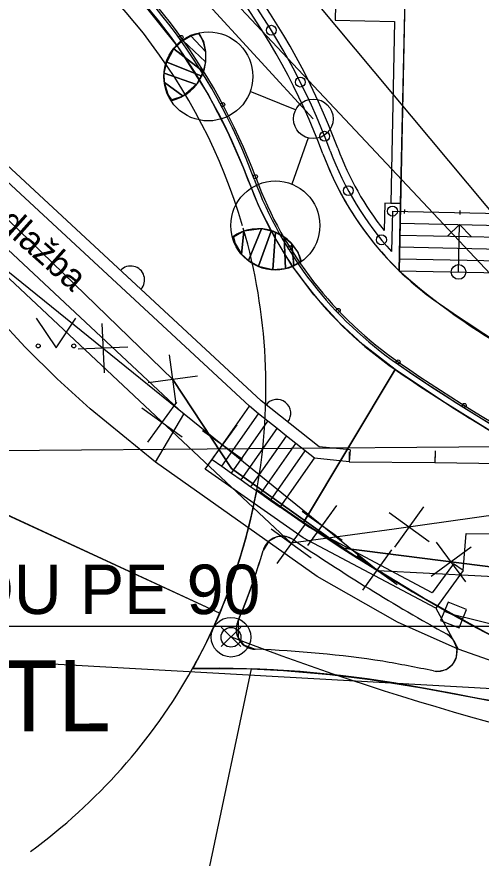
# Model space of a CAD drawing. Extents: x -643342 to -638635, y -1201752 to -1189948.
# Drawn here: x -639484.38 to -639472.65, y -1192725.54 to -1192704.29 of the extents above; entities that cross this region are included whole.
import ezdxf

# ---------------------------------------------------------------- set-up
doc = ezdxf.new("R2010")
doc.units = 0
for name, color, linetype in [('-zbytky_kruháče', 7, 'Continuous'), ('2', 7, 'Continuous'), ('IS_EL_NN_NADZEMNÍ', 7, 'Continuous'), ('IS_PLYN_STL', 7, 'Continuous'), ('IS_TELEF_MISTNI_ZAMERENO', 7, 'Continuous'), ('IS_VODOVOD_VAS', 7, 'Continuous'), ('K-HRANICE_KN', 7, 'Continuous'), ('N-CHODNIK', 7, 'Continuous'), ('N-CHODNIK-PŘÍMĚTICE', 7, 'Continuous'), ('N-HECTOMETRY', 7, 'Continuous'), ('N-KAN_DEST_TRASA-NÁVRH', 7, 'Continuous'), ('N-oploceni', 7, 'Continuous'), ('N-OSA', 7, 'Continuous'), ('N-rusene_vedeni', 7, 'Continuous'), ('N-SILNICE', 7, 'Continuous'), ('N-SRAFY_PLOCHY', 7, 'Continuous'), ('N-vo', 7, 'Continuous'), ('N-ZDI', 7, 'Continuous'), ('N-úprava plochu u obecního úřadu', 7, 'Continuous'), ('tomaštík - Džuganovi - Vrstva 36', 7, 'Continuous'), ('Z-hrany_a_čáry', 7, 'Continuous'), ('Z-popisy', 7, 'Continuous'), ('Z-vchody_vjezdy', 7, 'Continuous'), ('Z-značky', 7, 'Continuous'), ('Z-šachty_poklopy', 7, 'Continuous')]:
    doc.layers.add(name, color=color, linetype=linetype)

# ---------------------------------------------------------------- blocks, each defined once
blk = doc.blocks.new('hecto2')
at = {"layer": 'N-HECTOMETRY'}
blk.add_circle((0, 0), 0.25, dxfattribs=at)
blk = doc.blocks.new('POINT_DISPLAY')
for p, q in [((-0.245, -0.245), (0.245, 0.245)), ((-0.245, 0.245), (0.245, -0.245))]:
    blk.add_line(p, q)
blk = doc.blocks.new('zs')
at = {"layer": 'N-oploceni'}
blk.add_circle((0, 0), 0.05, dxfattribs=at)

msp = doc.modelspace()

# ---------------------------------------------------------------- linework, layer by layer
at = {"layer": '-zbytky_kruháče'}
for centre, radius, start, end in [((-639492.588, -1192713.663), 14.5, 16.3969, 59.8841), ((-639492.588, -1192713.663), 14.5, 349.7654, 16.1456), ((-639492.588, -1192713.663), 14.5, 330.7278, 349.7654), ((-639449.284, -1192676.149), 49.5, 234.0867, 250.3224), ((-639492.588, -1192713.663), 14.5, 306.1426, 330.7278), ((-639479.382, -1192748.546), 27.799, 79.9389, 91.1485), ((-639498.752, -1192857.717), 138.675, 76.30745, 79.93893)]:
    msp.add_arc(centre, radius, start, end, dxfattribs=at)
at = {"layer": '2'}
msp.add_line((-639514.564, -1192719.686), (-639469.586, -1192719.686), dxfattribs=at)
at = {"layer": 'IS_EL_NN_NADZEMNÍ'}
msp.add_line((-639467.47, -1192716.07), (-639488.19, -1192693.98), dxfattribs=at)
msp.add_lwpolyline([(-639485.829, -1192693.153), (-639467.777, -1192714.748)], dxfattribs=at)
at = {"layer": 'IS_PLYN_STL'}
msp.add_lwpolyline([(-639470.24, -1192716.66), (-639471.45, -1192716.75), (-639474.85, -1192717.23), (-639477.45, -1192717.59), (-639486.49, -1192709.11), (-639487.46, -1192707.33), (-639488.82, -1192705.38), (-639489.11, -1192702.85), (-639489.56, -1192702.88), (-639501.83, -1192703.9), (-639502.31, -1192703.92), (-639507.74, -1192703.7), (-639509.62, -1192703.19), (-639512.37, -1192701.73)], dxfattribs=at)
at = {"layer": 'IS_TELEF_MISTNI_ZAMERENO'}
for p, q in [((-639488.01, -1192706.12), (-639480.44, -1192713.45)), ((-639480.44, -1192713.45), (-639478.96, -1192715.7)), ((-639478.96, -1192715.7), (-639480.44, -1192713.45)), ((-639478.96, -1192715.7), (-639476.13, -1192717.71)), ((-639476.13, -1192717.71), (-639478.96, -1192715.7)), ((-639476.13, -1192717.71), (-639470.69, -1192718.41)), ((-639470.69, -1192718.41), (-639476.13, -1192717.71))]:
    msp.add_line(p, q, dxfattribs=at)
at = {"layer": 'IS_VODOVOD_VAS'}
msp.add_lwpolyline([(-639500.03, -1192699), (-639491.62, -1192697.56), (-639487.83, -1192708.11), (-639475.26, -1192718.28), (-639454.38, -1192719.35), (-639371.54, -1192712.72), (-639371.31, -1192712.71), (-639361.553, -1192711.318)], dxfattribs=at)
at = {"layer": 'K-HRANICE_KN'}
msp.add_line((-639430.11, -1192714.81), (-639485.5, -1192715.26), dxfattribs=at)
at = {"layer": 'N-CHODNIK'}
for p, q in [((-639474.553, -1192702.67), (-639474.724, -1192710.703)), ((-639474.84, -1192704.412), (-639474.938, -1192708.998)), ((-639475.088, -1192708.995), (-639475.102, -1192709.69)), ((-639474.938, -1192708.998), (-639474.688, -1192709.004)), ((-639474.698, -1192709.504), (-639471.699, -1192709.568)), ((-639473.199, -1192709.536), (-639473.505, -1192709.829)), ((-639473.224, -1192710.736), (-639473.199, -1192709.536)), ((-639473.199, -1192709.536), (-639472.905, -1192709.842)), ((-639474.705, -1192709.804), (-639471.706, -1192709.868)), ((-639474.711, -1192710.104), (-639471.712, -1192710.168)), ((-639474.717, -1192710.403), (-639471.719, -1192710.468)), ((-639474.724, -1192710.703), (-639471.725, -1192710.768))]:
    msp.add_line(p, q, dxfattribs=at)
msp.add_circle((-639473.224, -1192710.736), 0.185, dxfattribs=at)
at = {"layer": 'N-CHODNIK-PŘÍMĚTICE'}
for centre, radius, start, end in [((-639492.588, -1192713.663), 17, 20.3626, 53.6318), ((-639469.15, -1192704.964), 8, 200.3626, 225.8388)]:
    msp.add_arc(centre, radius, start, end, dxfattribs=at)
at = {"layer": 'N-HECTOMETRY'}
msp.add_circle((-639478.971, -1192719.962), 0.5, dxfattribs=at)
at = {"layer": 'N-KAN_DEST_TRASA-NÁVRH'}
msp.add_lwpolyline([(-639355.755, -1192712.633), (-639405.298, -1192719.503), (-639444.905, -1192722.803), (-639490.998, -1192720.223), (-639511.439, -1192713.331)], dxfattribs=at)
at = {"layer": 'N-oploceni'}
for p, q in [((-639474.591, -1192709.156), (-639474.593, -1192709.256)), ((-639474.892, -1192709.199), (-639474.914, -1192710.22)), ((-639474.892, -1192709.199), (-639471.493, -1192709.272)), ((-639473.191, -1192709.186), (-639473.194, -1192709.286))]:
    msp.add_line(p, q, dxfattribs=at)
for centre in [(-639477.951, -1192704.631), (-639477.22, -1192705.94), (-639476.606, -1192707.308), (-639476.008, -1192708.682), (-639474.892, -1192709.199), (-639475.171, -1192709.924)]:
    msp.add_circle(centre, 0.125, dxfattribs=at)
for centre, radius, start, end in [((-639492.588, -1192713.663), 17.2, 20.3626, 53.6318), ((-639492.588, -1192713.663), 15.2, 20.3626, 54.302), ((-639469.149, -1192704.964), 7.801, 200.3645, 222.363), ((-639469.15, -1192704.964), 9.8, 200.3626, 235.416), ((-639449.284, -1192676.149), 44.8, 235.416, 248.1495)]:
    msp.add_arc(centre, radius, start, end, dxfattribs=at)
at = {"layer": 'N-OSA'}
msp.add_arc((-639452.868, -1192651.78), 73, 249.0487, 271.88891, dxfattribs=at)
at = {"layer": 'N-rusene_vedeni'}
for p, q in [((-639482.23, -1192712.038), (-639482.178, -1192713.286)), ((-639481.579, -1192712.636), (-639482.828, -1192712.688)), ((-639480.356, -1192714.069), (-639480.524, -1192712.831)), ((-639479.821, -1192713.366), (-639481.059, -1192713.534)), ((-639480.346, -1192714.024), (-639481.078, -1192715.037)), ((-639481.219, -1192714.164), (-639480.205, -1192714.896)), ((-639478.822, -1192714.595), (-639479.554, -1192715.609)), ((-639479.695, -1192714.736), (-639478.681, -1192715.468)), ((-639479.52, -1192714.862), (-639478.856, -1192715.342)), ((-639478.948, -1192714.77), (-639479.428, -1192715.434)), ((-639477.176, -1192716.774), (-639476.163, -1192717.506)), ((-639476.304, -1192716.633), (-639477.035, -1192717.646)), ((-639476.43, -1192716.808), (-639476.909, -1192717.472)), ((-639474.98, -1192716.811), (-639473.966, -1192717.543)), ((-639474.107, -1192716.67), (-639474.839, -1192717.683)), ((-639477.001, -1192716.9), (-639476.337, -1192717.379)), ((-639477.957, -1192717.224), (-639476.943, -1192717.956)), ((-639477.084, -1192717.083), (-639477.816, -1192718.097)), ((-639473.038, -1192718.562), (-639473.782, -1192717.558)), ((-639474.916, -1192717.756), (-639475.648, -1192718.769)), ((-639472.908, -1192717.688), (-639473.912, -1192718.432)), ((-639475.788, -1192717.897), (-639474.775, -1192718.628)), ((-639475.614, -1192718.023), (-639474.95, -1192718.502)), ((-639475.042, -1192717.93), (-639475.521, -1192718.594))]:
    msp.add_line(p, q, dxfattribs=at)
at = {"layer": 'N-SILNICE'}
for centre, radius, start, end in [((-639492.588, -1192713.663), 15, 20.3626, 58.4763), ((-639492.588, -1192713.663), 15.15, 20.3626, 54.3132), ((-639469.15, -1192704.964), 10, 200.3626, 235.416), ((-639469.15, -1192704.964), 9.85, 200.3626, 235.416), ((-639449.284, -1192676.149), 45, 235.416, 271.6812), ((-639449.284, -1192676.149), 44.85, 235.416, 262.3092), ((-639449.284, -1192676.149), 44.85, 235.416, 271.2718), ((-639492.588, -1192713.663), 14.5, 330.7278, 349.7654), ((-639449.284, -1192676.149), 49.5, 234.0867, 250.3224), ((-639477.681, -1192717.909), 0.5, 55.7839, 164.1042), ((-639449.284, -1192676.149), 50, 235.7839, 241.0147), ((-639492.588, -1192713.663), 15, 336.8132, 344.1042), ((-639478.34, -1192719.766), 0.5, 156.8132, 267.9262), ((-639473.756, -1192720.324), 0.5, 258.1919, 61.0147), ((-639479.382, -1192748.546), 28.299, 81.3724, 87.9262), ((-639481.925, -1192759.399), 39.42, 78.1919, 80.0854), ((-639479.382, -1192748.546), 27.799, 79.9389, 91.1485), ((-639499.303, -1192860.56), 141.57, 76.54628, 79.92036)]:
    msp.add_arc(centre, radius, start, end, dxfattribs=at)
at = {"layer": 'N-SRAFY_PLOCHY'}
for p, q in [((-639474.552, -1192702.67), (-639474.724, -1192710.703)), ((-639480.316, -1192705.039), (-639481.458, -1192703.607)), ((-639474.688, -1192709.004), (-639474.584, -1192704.167)), ((-639474.84, -1192704.412), (-639474.938, -1192708.998)), ((-639479.56, -1192706.23), (-639480.316, -1192705.039)), ((-639479.049, -1192707.206), (-639479.56, -1192706.23)), ((-639478.655, -1192708.109), (-639479.049, -1192707.206)), ((-639478.268, -1192709.071), (-639478.655, -1192708.109)), ((-639477.884, -1192709.835), (-639478.268, -1192709.071)), ((-639475.088, -1192708.995), (-639475.102, -1192709.69)), ((-639474.688, -1192709.004), (-639475.088, -1192708.995)), ((-639474.938, -1192708.998), (-639474.688, -1192709.004)), ((-639474.724, -1192710.703), (-639474.688, -1192709.004)), ((-639477.432, -1192710.569), (-639477.884, -1192709.835)), ((-639476.875, -1192711.315), (-639477.432, -1192710.569)), ((-639476.226, -1192712.031), (-639476.875, -1192711.315)), ((-639475.645, -1192712.568), (-639476.226, -1192712.031)), ((-639474.827, -1192713.197), (-639475.645, -1192712.568)), ((-639474.826, -1192713.197), (-639477.142, -1192717.065)), ((-639477.142, -1192717.065), (-639474.827, -1192713.197)), ((-639473.628, -1192713.995), (-639474.826, -1192713.197)), ((-639472.421, -1192714.745), (-639473.628, -1192713.995)), ((-639478.45, -1192716.881), (-639478.319, -1192716.239)), ((-639478.319, -1192716.239), (-639477.682, -1192716.693)), ((-639485.157, -1192716.625), (-639479.25, -1192719.35)), ((-639485.157, -1192716.626), (-639479.25, -1192719.352)), ((-639477.682, -1192716.693), (-639477.142, -1192717.065)), ((-639478.641, -1192717.628), (-639478.45, -1192716.881)), ((-639477.142, -1192717.065), (-639475.922, -1192717.87)), ((-639478.941, -1192718.564), (-639478.641, -1192717.628)), ((-639475.922, -1192717.87), (-639474.387, -1192718.811)), ((-639479.25, -1192719.352), (-639478.941, -1192718.564)), ((-639474.387, -1192718.811), (-639473.229, -1192719.472)), ((-639479.25, -1192719.35), (-639479.571, -1192720.051)), ((-639473.229, -1192719.472), (-639471.716, -1192720.274)), ((-639479.571, -1192720.051), (-639479.939, -1192720.752)), ((-639479.939, -1192720.752), (-639479.176, -1192720.75)), ((-639478.462, -1192720.761), (-639479.514, -1192725.747)), ((-639478.463, -1192720.762), (-639479.514, -1192725.747)), ((-639479.176, -1192720.75), (-639478.462, -1192720.761)), ((-639478.065, -1192720.778), (-639478.463, -1192720.762)), ((-639477.222, -1192720.831), (-639478.065, -1192720.778)), ((-639476.475, -1192720.899), (-639477.222, -1192720.831)), ((-639475.757, -1192720.984), (-639476.475, -1192720.899)), ((-639475.155, -1192721.07), (-639475.757, -1192720.984)), ((-639474.526, -1192721.174), (-639475.155, -1192721.07)), ((-639473.783, -1192721.308), (-639474.526, -1192721.174)), ((-639473.038, -1192721.447), (-639473.783, -1192721.308)), ((-639471.837, -1192721.679), (-639473.038, -1192721.447))]:
    msp.add_line(p, q, dxfattribs=at)
for points in [[(-639476.204, -1192698.396), (-639476.343, -1192704.379), (-639474.84, -1192704.412)], [(-639472.367, -1192719.938), (-639474.117, -1192718.966), (-639475.491, -1192718.134), (-639476.532, -1192717.468), (-639477.142, -1192717.065), (-639477.682, -1192716.693), (-639478.319, -1192716.239), (-639478.545, -1192717.254), (-639478.791, -1192718.096), (-639479.096, -1192718.958), (-639479.411, -1192719.702), (-639479.649, -1192720.208), (-639479.94, -1192720.753), (-639479.177, -1192720.751), (-639478.463, -1192720.762), (-639477.644, -1192720.805), (-639476.475, -1192720.9), (-639475.456, -1192721.028), (-639474.155, -1192721.242), (-639472.841, -1192721.484), (-639471.453, -1192721.756)], [(-639477.4, -1192717.495), (-639477.58, -1192717.419), (-639477.812, -1192717.426), (-639478.014, -1192717.536), (-639478.162, -1192717.772)], [(-639478.793, -1192719.554), (-639478.793, -1192719.978), (-639478.658, -1192720.152), (-639478.358, -1192720.266)], [(-639473.858, -1192720.813), (-639473.729, -1192720.823), (-639473.54, -1192720.775), (-639473.372, -1192720.644), (-639473.273, -1192720.456), (-639473.261, -1192720.25), (-639473.361, -1192720.016), (-639473.513, -1192719.886)]]:
    msp.add_lwpolyline(points, dxfattribs=at)
for centre, radius, start, end in [((-639492.588, -1192713.663), 17.4, 20.3626, 53.6318), ((-639492.588, -1192713.663), 17, 20.3626, 53.6318), ((-639492.588, -1192713.663), 17, 20.3626, 53.6318), ((-639492.588, -1192713.663), 15, 20.3626, 54.3482), ((-639469.15, -1192704.964), 7.6, 200.3626, 218.4504), ((-639469.15, -1192704.964), 8, 200.3626, 235.416), ((-639469.15, -1192704.964), 8, 200.3626, 225.8388), ((-639469.15, -1192704.964), 10, 200.3626, 235.416), ((-639463.769, -1192698.406), 16.47, 228.3034, 240.9372), ((-639449.284, -1192676.149), 43, 235.416, 246.7221), ((-639449.284, -1192676.149), 45, 235.416, 245.5943), ((-639477.681, -1192717.909), 0.5, 55.7839, 164.1042), ((-639449.283, -1192676.148), 50.001, 235.784, 241.0146), ((-639449.284, -1192676.149), 50, 235.7839, 241.0147), ((-639492.588, -1192713.663), 15, 336.8132, 344.1042), ((-639492.588, -1192713.663), 15, 336.8787, 344.1042), ((-639478.34, -1192719.766), 0.5, 156.8132, 267.9243), ((-639473.756, -1192720.324), 0.5, 258.1522, 61.0147), ((-639479.382, -1192748.546), 28.299, 81.3724, 87.9262), ((-639478.34, -1192719.766), 0.5, 267.9245, 267.9263), ((-639479.382, -1192748.546), 28.299, 87.92619045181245, 87.92619290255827), ((-639478.34, -1192719.766), 0.5, 267.9243, 267.9245), ((-639479.382, -1192748.546), 28.299, 87.92616076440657, 87.92619045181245), ((-639478.34, -1192719.766), 0.5, 267.9245, 267.9262), ((-639479.382, -1192748.546), 28.299, 81.3724, 87.9262), ((-639481.77, -1192758.593), 38.599, 78.1722, 80.1055), ((-639481.925, -1192759.399), 39.42, 78.1919, 80.0854)]:
    msp.add_arc(centre, radius, start, end, dxfattribs=at)
at = {"layer": 'N-vo'}
for p, q in [((-639484.101, -1192699.004), (-639476.892, -1192706.867)), ((-639477.338, -1192706.64), (-639478.488, -1192706.18)), ((-639477.018, -1192707.35), (-639477.438, -1192708.516))]:
    msp.add_line(p, q, dxfattribs=at)
for points in [[(-639480.188, -1192704.885), (-639479.613, -1192705.43), (-639479.673, -1192705.674), (-639480.418, -1192705.103)], [(-639479.988, -1192704.771), (-639479.619, -1192705.168), (-639479.613, -1192705.43), (-639480.188, -1192704.885)], [(-639479.789, -1192704.713), (-639479.662, -1192704.916), (-639479.619, -1192705.168), (-639479.988, -1192704.771)], [(-639480.418, -1192705.103), (-639479.673, -1192705.674), (-639479.724, -1192705.78), (-639480.593, -1192705.435)], [(-639480.593, -1192705.435), (-639479.724, -1192705.78), (-639479.841, -1192706.001), (-639480.656, -1192705.714)], [(-639480.656, -1192705.714), (-639479.841, -1192706.001), (-639480.182, -1192706.294), (-639480.652, -1192705.954)], [(-639480.652, -1192705.954), (-639480.182, -1192706.294), (-639480.469, -1192706.391), (-639480.558, -1192706.254)], [(-639478.706, -1192710.284), (-639478.648, -1192709.707), (-639478.912, -1192709.857), (-639478.868, -1192710.015)], [(-639478.529, -1192710.447), (-639478.202, -1192709.647), (-639478.648, -1192709.707), (-639478.706, -1192710.284)], [(-639478.279, -1192710.585), (-639477.959, -1192709.706), (-639478.202, -1192709.647), (-639478.529, -1192710.447)], [(-639477.914, -1192710.674), (-639477.846, -1192709.739), (-639477.959, -1192709.706), (-639478.279, -1192710.585)], [(-639477.598, -1192710.648), (-639477.624, -1192709.856), (-639477.846, -1192709.739), (-639477.914, -1192710.674)], [(-639477.38, -1192710.574), (-639477.432, -1192710.034), (-639477.624, -1192709.856), (-639477.598, -1192710.648)], [(-639477.205, -1192710.463), (-639477.273, -1192710.233), (-639477.432, -1192710.034), (-639477.38, -1192710.574)]]:
    msp.add_lwpolyline(points, close=True, dxfattribs=at)
for centre, radius in [((-639479.544, -1192705.795), 1.125), ((-639476.892, -1192706.867), 0.5), ((-639477.851, -1192709.562), 1.125)]:
    msp.add_circle(centre, radius, dxfattribs=at)
for centre, start, end in [((-639480.728, -1192705.311), 282.4447, 33.157), ((-639478.276, -1192710.768), 15.2433, 125.9557)]:
    msp.add_arc(centre, 1.125, start, end, dxfattribs=at)
at = {"layer": 'N-ZDI'}
for centre, radius, start, end in [((-639492.588, -1192713.663), 17.4, 20.3626, 53.6318), ((-639469.15, -1192704.964), 7.6, 200.3626, 218.4504)]:
    msp.add_arc(centre, radius, start, end, dxfattribs=at)
at = {"layer": 'N-úprava plochu u obecního úřadu'}
msp.add_lwpolyline([(-639476.204, -1192698.396), (-639476.343, -1192704.379), (-639474.84, -1192704.412)], dxfattribs=at)
at = {"layer": 'Z-hrany_a_čáry'}
for p, q in [((-639478.205, -1192713.992), (-639487.434, -1192705.437)), ((-639478.502, -1192714.125), (-639487.71, -1192705.59)), ((-639480.16, -1192714.33), (-639489.06, -1192706.01)), ((-639484.173, -1192712.635), (-639485.143, -1192711.589)), ((-639483.365, -1192713.438), (-639484.173, -1192712.635)), ((-639482.525, -1192714.196), (-639483.365, -1192713.438)), ((-639476.742, -1192715.151), (-639478.205, -1192713.992)), ((-639480.88, -1192715.54), (-639482.525, -1192714.196)), ((-639479.448, -1192715.472), (-639478.502, -1192714.125)), ((-639478.273, -1192714.32), (-639478.502, -1192714.125)), ((-639480.88, -1192715.54), (-639480.16, -1192714.33)), ((-639479.203, -1192715.644), (-639478.273, -1192714.32)), ((-639478.037, -1192714.507), (-639478.273, -1192714.32)), ((-639478.957, -1192715.817), (-639478.037, -1192714.507)), ((-639478.712, -1192715.989), (-639477.802, -1192714.693)), ((-639477.802, -1192714.693), (-639478.037, -1192714.507)), ((-639477.567, -1192714.88), (-639477.802, -1192714.693)), ((-639478.466, -1192716.161), (-639477.567, -1192714.88)), ((-639477.331, -1192715.067), (-639477.567, -1192714.88)), ((-639478.221, -1192716.334), (-639477.331, -1192715.067)), ((-639477.095, -1192715.253), (-639477.331, -1192715.067)), ((-639477.975, -1192716.506), (-639477.095, -1192715.253)), ((-639476.86, -1192715.44), (-639477.095, -1192715.253)), ((-639475.959, -1192715.232), (-639476.742, -1192715.151)), ((-639475.959, -1192715.232), (-639475.99, -1192715.53)), ((-639473.816, -1192715.25), (-639473.82, -1192715.55)), ((-639476.792, -1192718.431), (-639480.88, -1192715.54)), ((-639479.62, -1192715.716), (-639479.449, -1192715.473)), ((-639479.448, -1192715.472), (-639479.203, -1192715.644)), ((-639477.73, -1192716.679), (-639476.86, -1192715.44)), ((-639475.99, -1192715.53), (-639476.86, -1192715.44)), ((-639477.15, -1192717.45), (-639479.62, -1192715.716)), ((-639479.203, -1192715.644), (-639478.957, -1192715.817)), ((-639473.82, -1192715.55), (-639454.73, -1192715.8)), ((-639478.957, -1192715.817), (-639478.712, -1192715.989)), ((-639478.712, -1192715.989), (-639478.466, -1192716.161)), ((-639478.466, -1192716.161), (-639478.221, -1192716.334)), ((-639478.221, -1192716.334), (-639477.975, -1192716.506)), ((-639477.975, -1192716.506), (-639477.73, -1192716.679)), ((-639477.009, -1192717.185), (-639477.73, -1192716.679)), ((-639473.889, -1192718.843), (-639477.009, -1192717.185)), ((-639473.8, -1192719.23), (-639477.15, -1192717.45)), ((-639473.11, -1192718.28), (-639473.03, -1192717.34)), ((-639473.03, -1192717.34), (-639467.48, -1192717.38)), ((-639473.353, -1192718.104), (-639473.889, -1192718.843)), ((-639473.11, -1192718.28), (-639473.8, -1192719.23)), ((-639473.11, -1192718.28), (-639473.353, -1192718.104)), ((-639474.767, -1192719.579), (-639476.792, -1192718.431)), ((-639473.8, -1192719.23), (-639473.23, -1192720.26)), ((-639473.23, -1192720.26), (-639474.767, -1192719.579)), ((-639471.72, -1192719.8), (-639473.35, -1192719.4)), ((-639472.32, -1192720.58), (-639473.23, -1192720.26))]:
    msp.add_line(p, q, dxfattribs=at)
for centre, start, end in [((-639481.503, -1192710.935), 317.1704, 137.1704), ((-639477.81, -1192714.305), 321.6135, 141.6135)]:
    msp.add_arc(centre, 0.35, start, end, dxfattribs=at)
at = {"layer": 'Z-vchody_vjezdy'}
for p, q in [((-639475.988, -1192715.28), (-639475.99, -1192715.53)), ((-639473.818, -1192715.3), (-639473.82, -1192715.55)), ((-639475.99, -1192715.53), (-639473.82, -1192715.55))]:
    msp.add_line(p, q, dxfattribs=at)
at = {"layer": 'Z-značky'}
for p, q in [((-639483.891, -1192711.904), (-639483.391, -1192712.654)), ((-639483.391, -1192712.654), (-639482.891, -1192711.904))]:
    msp.add_line(p, q, dxfattribs=at)
for centre in [(-639483.841, -1192712.604), (-639482.942, -1192712.604)]:
    msp.add_circle(centre, 0.05, dxfattribs=at)
at = {"layer": 'Z-šachty_poklopy'}
for p, q in [((-639473.488, -1192719.075), (-639473.676, -1192719.539)), ((-639473.025, -1192719.262), (-639473.488, -1192719.075)), ((-639473.582, -1192719.307), (-639473.118, -1192719.494)), ((-639473.212, -1192719.726), (-639473.025, -1192719.262)), ((-639473.676, -1192719.539), (-639473.212, -1192719.726))]:
    msp.add_line(p, q, dxfattribs=at)

# ---------------------------------------------------------------- block references
at = {"layer": 'N-CHODNIK'}
msp.add_blockref('POINT_DISPLAY', (-639478.971, -1192719.954), dxfattribs=at)
at = {"layer": 'N-HECTOMETRY'}
msp.add_blockref('hecto2', (-639478.971, -1192719.962), dxfattribs=at)
at = {"layer": 'N-úprava plochu u obecního úřadu'}
for p, rotation in [((-639480.232, -1192704.81), -54.37868598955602), ((-639479.178, -1192706.508), -61.91760434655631), ((-639478.355, -1192708.329), -69.45652270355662), ((-639477.482, -1192710.125), -58.22482841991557), ((-639476.263, -1192711.706), -46.53181176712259), ((-639474.749, -1192713.008), -34.83879511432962), ((-639473.079, -1192714.108), -32.081913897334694)]:
    msp.add_blockref('zs', p, dxfattribs=dict(at, rotation=rotation))

# ---------------------------------------------------------------- texts
at = {"layer": '2'}
msp.add_text('PŘELOŽKA 7 STL', height=1.8, rotation=0.0705, dxfattribs=at).set_placement((-639501.934, -1192722.364))
at = {"layer": 'tomaštík - Džuganovi - Vrstva 36'}
msp.add_text('ZASLEPENÍ STÁVAJÍCÍHO PLYNOVODU PE 90', height=1.25, rotation=359.9647, dxfattribs=at).set_placement((-639514.831, -1192719.356))
at = {"layer": 'Z-popisy'}
msp.add_text('dlažba', height=0.65, rotation=318.3176, dxfattribs=at).set_placement((-639484.888, -1192709.552))

doc.saveas('drawing.dxf')
